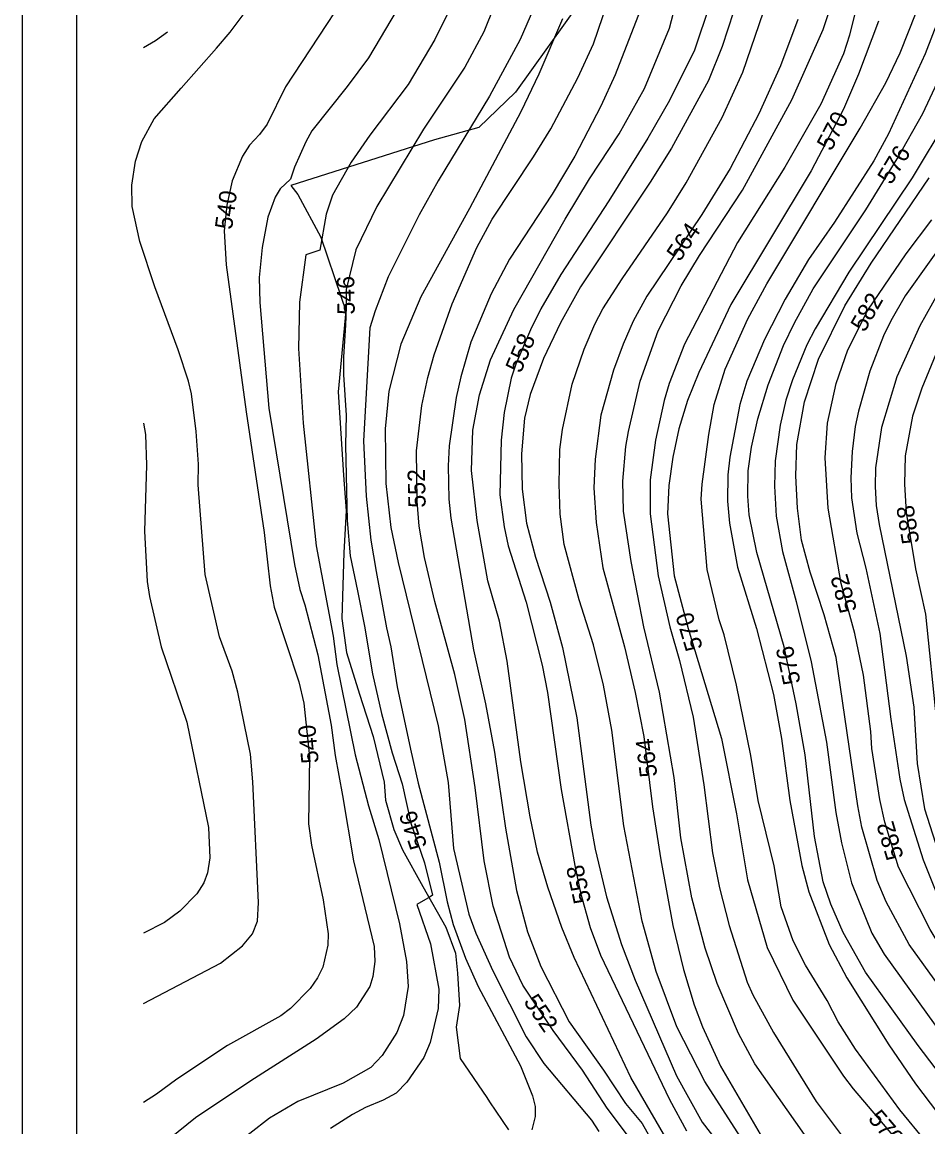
# Model space of a CAD drawing. Extents: x -709418 to -703832, y -1161719 to -1157826.
# Drawn here: x -709418 to -709000, y -1161138 to -1160629 of the extents above; entities that cross this region are included whole.
import ezdxf

# ---------------------------------------------------------------- set-up
doc = ezdxf.new("R2010")
doc.units = 0
for name, color, linetype in [('103_hranice KÚ', 7, 'Continuous'), ('120_vrstevnice hlavní', 7, 'Continuous'), ('121_vrstevnice hlavní_popis', 7, 'Continuous'), ('122_vrstevnice základní', 7, 'Continuous'), ('124_vrstevnice doplňková', 7, 'Continuous'), ('800_mřížka', 7, 'Continuous')]:
    doc.layers.add(name, color=color, linetype=linetype)

msp = doc.modelspace()

# ---------------------------------------------------------------- linework, layer by layer
at = {"layer": '103_hranice KÚ'}
msp.add_lwpolyline([(-709152.76, -1160608.68), (-709190.29, -1160661.38), (-709207.27, -1160677.68), (-709227.61, -1160683.32), (-709293.86, -1160704.4), (-709290.67, -1160708.55), (-709280.09, -1160728.22), (-709270.72, -1160755.76), (-709268.6, -1160762.02), (-709272.02, -1160799.36), (-709269.54, -1160837.72), (-709268.34, -1160854.2), (-709269.41, -1160873.36), (-709270.41, -1160903.76), (-709268.23, -1160919.43), (-709262.21, -1160938.65), (-709255.95, -1160958.22), (-709250.87, -1160979.18), (-709250.21, -1160987.55), (-709246.42, -1161000.99), (-709242.46, -1161010.31), (-709232.98, -1161027.29), (-709222.38, -1161046.02), (-709218.04, -1161058.04), (-709217.06, -1161067.22), (-709216.15, -1161082.04), (-709217.68, -1161092.12), (-709215.78, -1161106.54), (-709203.57, -1161124.53), (-709202.27, -1161126.44), (-709193.49, -1161139.37)], dxfattribs=at)
at = {"layer": '120_vrstevnice hlavní'}
for points in [[(-709254.71, -1160595.41), (-709296.28, -1160658.95), (-709304.81, -1160676.16), (-709308.28, -1160680.93), (-709312.91, -1160685.7), (-709316.09, -1160690.91), (-709320.88, -1160702.17), (-709323.4, -1160713.42), (-709324.66, -1160725.16), (-709323.61, -1160740.96), (-709314.5, -1160808.65), (-709306.11, -1160864.2), (-709303.36, -1160888.79), (-709301.48, -1160898.62), (-709290.2, -1160933.05), (-709287.89, -1160942.88), (-709285.28, -1160967.47), (-709285.72, -1160998.43), (-709284.41, -1161008.26), (-709278.92, -1161033.43), (-709276.6, -1161049.05), (-709276.75, -1161054.26), (-709279.06, -1161064.38), (-709281.52, -1161069.3), (-709284.99, -1161074.22), (-709294.1, -1161083.48), (-709298.44, -1161086.8), (-709323.03, -1161100.54), (-709346.47, -1161116.02), (-709355.72, -1161122.96), (-709361.7, -1161126.76)], [(-709089.87, -1160624.38), (-709095.07, -1160640.29), (-709101.44, -1160655.91), (-709118.51, -1160687.15), (-709128.34, -1160702.77), (-709160.45, -1160751.08), (-709169.57, -1160767.57), (-709177.38, -1160784.06), (-709183.6, -1160800.55), (-709186.2, -1160811.55), (-709187.5, -1160828.03), (-709187.21, -1160844.24), (-709185.19, -1160859.86), (-709181.14, -1160875.48), (-709174.34, -1160896.31), (-709168.7, -1160917.14), (-709162.05, -1160949.54), (-709155.54, -1160999), (-709153.66, -1161010), (-709148.45, -1161031.98), (-709141.51, -1161053.97), (-709135.14, -1161070.46), (-709116.19, -1161114.43), (-709104.33, -1161135.84), (-709079.02, -1161168.53)], [(-709168.7, -1160627.56), (-709179.55, -1160653.02), (-709187.94, -1160670.37), (-709211.51, -1160714.92), (-709233.93, -1160755.71), (-709243.19, -1160777.41), (-709248.69, -1160799.11), (-709250.42, -1160816.46), (-709250.13, -1160841.63), (-709247.82, -1160861.88), (-709244.35, -1160878.08), (-709225.98, -1160953.3), (-709221.35, -1160979.33), (-709218.89, -1161009.71), (-709211.8, -1161040.08), (-709208.62, -1161048.76), (-709200.81, -1161066.12), (-709185.48, -1161096.49), (-709177.23, -1161108.79), (-709155.25, -1161134.97), (-709151.92, -1161140.18)], [(-709023.04, -1160628.71), (-709032.3, -1160653.02), (-709039.1, -1160669.22), (-709053.99, -1160697.56), (-709091.02, -1160759.18), (-709105.78, -1160790.43), (-709111.13, -1160803.45), (-709115.04, -1160816.46), (-709117.78, -1160829.48), (-709119.66, -1160842.5), (-709120.24, -1160855.52), (-709117.21, -1160884.16), (-709110.7, -1160908.46), (-709095.36, -1160959.08), (-709088.42, -1160993.8), (-709083.36, -1161024.17), (-709074.35, -1161055.36), (-709062.5, -1161079.58), (-709039.24, -1161114.57), (-709034.76, -1161120.51), (-708995.85, -1161166.21)], [(-708986.59, -1161084.92), (-709008.87, -1161053.97), (-709019.43, -1161034.3), (-709023.62, -1161024.46), (-709030.71, -1160999.87), (-709032.59, -1160990.04), (-709042.57, -1160921.76), (-709048.07, -1160902.09), (-709054.57, -1160882.42), (-709058.48, -1160867.67), (-709060.36, -1160852.91), (-709061.08, -1160838.16), (-709060.65, -1160823.7), (-709057.18, -1160804.02), (-709050.67, -1160784.35), (-709038.52, -1160759.76), (-709026.37, -1160740.09), (-708999.75, -1160700.75)]]:
    msp.add_lwpolyline(points, dxfattribs=at)
at = {"layer": '122_vrstevnice základní'}
for points in [[(-709020.87, -1160572.01), (-709036.35, -1160635.08), (-709039.1, -1160643.76), (-709049.66, -1160666.9), (-709066.15, -1160695.83), (-709087.99, -1160730.54), (-709112.43, -1160777.41), (-709119.52, -1160795.63), (-709121.83, -1160803.45), (-709125.88, -1160821.67), (-709128.2, -1160839.9), (-709128.34, -1160855.52), (-709124.58, -1160884.16), (-709119.23, -1160907.59), (-709114.75, -1160923.21), (-709108.38, -1160949.25), (-709103.46, -1160980.49), (-709099.56, -1161011.73), (-709096.38, -1161027.93), (-709091.89, -1161045.29), (-709083.5, -1161071.33), (-709080.9, -1161077.11), (-709071.5, -1161094.47), (-709051.83, -1161126.29), (-709036.06, -1161147.12)], [(-709195.75, -1160610.49), (-709205, -1160633.63), (-709213.68, -1160649.83), (-709232.78, -1160678.47), (-709254.18, -1160714.05), (-709263.87, -1160734.02), (-709268.36, -1160752.24), (-709268.36, -1160760.2), (-709268.65, -1160768.73), (-709269.66, -1160783.2), (-709269.66, -1160791.58), (-709268.36, -1160810.1), (-709268.65, -1160823.98), (-709267.92, -1160858.7), (-709266.48, -1160874.9), (-709263.15, -1160891.1), (-709259.97, -1160907.3), (-709256.21, -1160929.29), (-709252.16, -1160947.51), (-709247.24, -1160965.74), (-709242.61, -1160979.91), (-709238.56, -1160998.14), (-709232.34, -1161016.36), (-709228.58, -1161031.26), (-709229.59, -1161031.98), (-709235.75, -1161035.57), (-709229.45, -1161053.68), (-709225.69, -1161074.51), (-709225.98, -1161083.48), (-709229.59, -1161099.1), (-709232.63, -1161106.04), (-709240.44, -1161117.47), (-709245.36, -1161122.39), (-709251.29, -1161125.71), (-709259.39, -1161129.04), (-709265.47, -1161132.22), (-709275.59, -1161138.73)], [(-709136.88, -1161144.23), (-709148.16, -1161129.33), (-709159.44, -1161111.83), (-709173.04, -1161093.6), (-709186.92, -1161072.77), (-709193.14, -1161059.76), (-709200.67, -1161036.32), (-709204.72, -1161015.49), (-709208.91, -1160981.65), (-709213.68, -1160950.4), (-709218.31, -1160929.57), (-709227.57, -1160896.02), (-709232.2, -1160875.77), (-709234.66, -1160861.3), (-709235.67, -1160849.73), (-709235.96, -1160826.59), (-709233.5, -1160805.76), (-709230.75, -1160792.74), (-709227.86, -1160782.33), (-709219.47, -1160758.89), (-709208.19, -1160732.86), (-709201.1, -1160719.84), (-709182.01, -1160691.2), (-709174.05, -1160678.18), (-709161.61, -1160654.75), (-709154.38, -1160639.13), (-709143.48, -1160606.97)], [(-709046.18, -1161156.96), (-709080.03, -1161108.93), (-709087.55, -1161095.05), (-709097.39, -1161071.91), (-709102.89, -1161055.71), (-709109.1, -1161032.56), (-709114.17, -1161004.79), (-709117.2, -1160977.02), (-709124, -1160937.68), (-709131.23, -1160907.59), (-709137.02, -1160877.5), (-709140.49, -1160854.36), (-709140.93, -1160840.47), (-709139.48, -1160824.56), (-709138.32, -1160817.62), (-709132.83, -1160794.48), (-709124.58, -1160771.33), (-709114.02, -1160750.51), (-709105.49, -1160736.62), (-709085.67, -1160706.53), (-709062.96, -1160664.88), (-709048.5, -1160632.48), (-709040.83, -1160609.33)], [(-709120.97, -1161143.07), (-709137.17, -1161115.3), (-709163.35, -1161060.04), (-709168.99, -1161046.16), (-709175.5, -1161027.64), (-709180.12, -1161011.44), (-709183.6, -1160995.24), (-709187.94, -1160969.79), (-709194.16, -1160923.5), (-709197.77, -1160904.99), (-709203.12, -1160886.47), (-709208.04, -1160858.7), (-709210.65, -1160835.56), (-709209.92, -1160817.04), (-709206.88, -1160800.84), (-709201.82, -1160784.64), (-709191.12, -1160761.5), (-709167.4, -1160719.84), (-709156.26, -1160701.33), (-709142.52, -1160680.5), (-709130.95, -1160659.67), (-709119.37, -1160631.9), (-709114.02, -1160611.07)], [(-708992.09, -1160619.46), (-709001.49, -1160643.76), (-709018.41, -1160680.5), (-709025.21, -1160692.94), (-709043.29, -1160721.29), (-709055.3, -1160738.5), (-709066, -1160756.72), (-709075.55, -1160775.24), (-709083.65, -1160794.48), (-709086.97, -1160805.18), (-709091.6, -1160829.48), (-709092.47, -1160837.58), (-709092.61, -1160849.73), (-709091.75, -1160859.86), (-709087.99, -1160880.11), (-709079.31, -1160908.46), (-709071.35, -1160938.83), (-709067.74, -1160959.08), (-709063.83, -1160987.72), (-709058.33, -1161017.52), (-709055.15, -1161029.67), (-709045.75, -1161053.97), (-709037.65, -1161069.3), (-709018.27, -1161100.26), (-709005.97, -1161118.19), (-708995.85, -1161131.5)], [(-709318.26, -1160937.68), (-709320.86, -1160928.13), (-709326.79, -1160912.22), (-709333.3, -1160883.58), (-709336.63, -1160842.21), (-709336.49, -1160832.66), (-709337.5, -1160817.62), (-709339.67, -1160800.26), (-709340.97, -1160794.48), (-709345.74, -1160780.01), (-709356.59, -1160751.08), (-709363.4, -1160730.16), (-709367.05, -1160714.01), (-709367.1, -1160704.14), (-709365.45, -1160693.07), (-709362.6, -1160684.04), (-709356.83, -1160673.68), (-709344.42, -1160659.49), (-709328.11, -1160641.08), (-709321.76, -1160633.76), (-709315.8, -1160625.68)], [(-709244.93, -1160623.22), (-709258.09, -1160645.49), (-709267.92, -1160658.8), (-709284.12, -1160679.2), (-709287.02, -1160684.26), (-709292.22, -1160695.83), (-709293.96, -1160701.47), (-709298.73, -1160705.81), (-709301.05, -1160709.72), (-709304.52, -1160718.97), (-709307.12, -1160732.86), (-709308.42, -1160746.74), (-709308.14, -1160758.32), (-709303.94, -1160806.92), (-709292.22, -1160878.95), (-709289.77, -1160890.52), (-709287.45, -1160897.46), (-709281.38, -1160920.61), (-709275.3, -1160953.01), (-709273.42, -1160966.89), (-709270.09, -1160985.41), (-709265.03, -1161015.49), (-709255.48, -1161054.84), (-709255.2, -1161061.78), (-709256.06, -1161068.72), (-709257.51, -1161073.35), (-709263.59, -1161082.9), (-709269.23, -1161088.25), (-709282.24, -1161097.65), (-709312.33, -1161116.75), (-709337.79, -1161133.81), (-709361.7, -1161153.18)], [(-709221.93, -1160625.82), (-709227.57, -1160637.1), (-709239.86, -1160657.79), (-709257.51, -1160681.22), (-709266.04, -1160693.66), (-709274.72, -1160708.85), (-709277.61, -1160717.53), (-709280.48, -1160734.12), (-709287.02, -1160736.27), (-709289.91, -1160758.03), (-709290.34, -1160779.43), (-709288.17, -1160813.86), (-709282.24, -1160870.27), (-709274.43, -1160911.93), (-709272.7, -1160924.95), (-709264.16, -1160966.6), (-709258.09, -1160990.04), (-709253.32, -1161005.66), (-709243.77, -1161044.42), (-709240.59, -1161061.78), (-709239.86, -1161073.35), (-709241.89, -1161086.66), (-709245.07, -1161094.47), (-709251.72, -1161105.17), (-709257.08, -1161110.67), (-709269.81, -1161117.9), (-709290.63, -1161126.29), (-709303.65, -1161133.96), (-709321.88, -1161148.13)], [(-709182.01, -1160622.93), (-709188.22, -1160637.1), (-709202.26, -1160663.14), (-709225.98, -1160702.19), (-709234.8, -1160717.81), (-709248.98, -1160746.46), (-709255.05, -1160762.08), (-709257.51, -1160769.89), (-709260.4, -1160821.96), (-709259.1, -1160847.42), (-709257.08, -1160867.67), (-709254.47, -1160882.13), (-709249.84, -1160908.17), (-709247.82, -1160916.85), (-709244.93, -1160935.36), (-709238.71, -1160964), (-709235.23, -1160979.62), (-709225.54, -1161016.07), (-709221.78, -1161034.3), (-709219.03, -1161044.71), (-709213.39, -1161060.33), (-709207.46, -1161073.35), (-709188.08, -1161109.8), (-709182.44, -1161123.69), (-709181.28, -1161128.6), (-709181.28, -1161133.23), (-709182.73, -1161139.31)], [(-709132.83, -1160623.8), (-709144.4, -1160653.3), (-709151.05, -1160667.77), (-709163.06, -1160690.91), (-709173.47, -1160708.27), (-709193.14, -1160738.35), (-709201.53, -1160754.27), (-709210.93, -1160776.54), (-709215.56, -1160792.45), (-709217.73, -1160802), (-709220.91, -1160824.27), (-709221.35, -1160833.53), (-709221.06, -1160848.86), (-709220.19, -1160857.54), (-709209.63, -1160918.29), (-709204.14, -1160943.17), (-709199.94, -1160965.45), (-709194.88, -1161000.45), (-709189.82, -1161029.09), (-709184.75, -1161048.18), (-709178.68, -1161064.09), (-709165.66, -1161089.55), (-709149.75, -1161111.83), (-709139.62, -1161127.16), (-709131.96, -1161136.42), (-709123.28, -1161151.75)], [(-709100.72, -1160620.9), (-709107.8, -1160642.02), (-709119.37, -1160665.17), (-709129.35, -1160682.52), (-709147.29, -1160711.45), (-709169.42, -1160745.3), (-709178.68, -1160761.21), (-709183.45, -1160770.76), (-709190.25, -1160786.67), (-709192.28, -1160793.03), (-709195.6, -1160808.94), (-709196.9, -1160821.67), (-709197.48, -1160846.84), (-709195.6, -1160861.59), (-709193.72, -1160870.27), (-709185.48, -1160896.31), (-709178.1, -1160925.24), (-709175.64, -1160937.96), (-709169.28, -1160982.52), (-709163.06, -1161017.52), (-709160.31, -1161030.25), (-709155.97, -1161046.16), (-709151.2, -1161058.89)], [(-709086.83, -1161142.49), (-709103.03, -1161117.03), (-709115.9, -1161091.87), (-709125.45, -1161066.41), (-709131.96, -1161043.27), (-709140.35, -1160999.29), (-709145.99, -1160955.32), (-709149.75, -1160934.49), (-709154.38, -1160915.98), (-709161.03, -1160895.15), (-709167.83, -1160869.69), (-709169.71, -1160855.81), (-709170.14, -1160841.92), (-709169.85, -1160826.01), (-709168.7, -1160816.75), (-709164.21, -1160795.92), (-709158.72, -1160779.72), (-709153.8, -1160768.15), (-709150.04, -1160761.21), (-709141.22, -1160747.32), (-709120.24, -1160716.95), (-709111.71, -1160703.06), (-709095.07, -1160672.98), (-709085.53, -1160652.15), (-709075.98, -1160624.38)], [(-709001.06, -1161144.81), (-709013.21, -1161130.2), (-709033.6, -1161102.14), (-709041.56, -1161089.55), (-709046.62, -1161079.72), (-709056.74, -1161063.52), (-709062.29, -1161052.26), (-709067.83, -1161036.6), (-709071.06, -1161017.81), (-709078.44, -1160987.72), (-709081.91, -1160966.89), (-709088.42, -1160934.49), (-709094.21, -1160911.35), (-709096.52, -1160904.41), (-709102.02, -1160881.26), (-709104.77, -1160848.86), (-709104.33, -1160841.92), (-709101.29, -1160819.07), (-709098.84, -1160805.18), (-709093.77, -1160788.98), (-709083.21, -1160765.84), (-709074.54, -1160749.64), (-709031.43, -1160677.89), (-709019.71, -1160657.06), (-709013.06, -1160643.18), (-709005.68, -1160624.66)], [(-709060.22, -1160627.85), (-709068.17, -1160649.25), (-709078.15, -1160671.38), (-709091.46, -1160696.55), (-709104.48, -1160717.67), (-709129.79, -1160755.28), (-709136.15, -1160766.85), (-709140.78, -1160777.41), (-709145.12, -1160789.41), (-709151.05, -1160810.1), (-709153.66, -1160830.35), (-709154.23, -1160843.66), (-709153.08, -1160859.57), (-709150.04, -1160880.4), (-709140.06, -1160916.85), (-709135.14, -1160937.96), (-709131.23, -1160958.21), (-709127.19, -1160990.61), (-709123.42, -1161014.92), (-709117.78, -1161045.29), (-709112.86, -1161065.54), (-709107.95, -1161081.74), (-709104.19, -1161091.87), (-709095.8, -1161110.09), (-709077.57, -1161141.33)], [(-709028.97, -1161066.7), (-709039.39, -1161048.47), (-709045.03, -1161035.46), (-709048.5, -1161025.04), (-709052.55, -1161004.21), (-709056.89, -1160966.6), (-709060.94, -1160943.17), (-709066.58, -1160916.85), (-709079.16, -1160873.45), (-709082.64, -1160856.09), (-709083.21, -1160847.42), (-709083.07, -1160835.84), (-709081.62, -1160824.85), (-709078.59, -1160811.83), (-709073.81, -1160796.21), (-709066.87, -1160777.99), (-709061.81, -1160767.57), (-709053.13, -1160751.95), (-709028.83, -1160715.5), (-709014.36, -1160692.07), (-709002.65, -1160671.24), (-708988.04, -1160640)], [(-708991.07, -1160673.55), (-709007.56, -1160700.75), (-709036.64, -1160744.29), (-709052.26, -1160770.32), (-709056.02, -1160777.7), (-709062.67, -1160793.9), (-709065.71, -1160803.16), (-709068.32, -1160814.73), (-709070.63, -1160831.22), (-709070.92, -1160842.79), (-709070.2, -1160856.67), (-709067.3, -1160872.87), (-709060.94, -1160896.02), (-709054.14, -1160923.79), (-709047.05, -1160960.82), (-709042.71, -1160993.22), (-709040.11, -1161007.1), (-709035.48, -1161025.62), (-709026.08, -1161048.76), (-709020.44, -1161058.45), (-708989.05, -1161101.99)], [(-708975.31, -1160705.38), (-709010.75, -1160755.13), (-709017.4, -1160766.71), (-709020.73, -1160773.65), (-709027.09, -1160789.85), (-709032.3, -1160808.36), (-709033.74, -1160815.31), (-709035.19, -1160826.88), (-709035.77, -1160839.03), (-709035.48, -1160848.29), (-709033.02, -1160864.49)], [(-709037.22, -1160780.01), (-709027.96, -1160761.79), (-709010.31, -1160735.75), (-708998.45, -1160720.13)], [(-708995.27, -1160753.4), (-709003.95, -1160769.02), (-709014.65, -1160792.45), (-709021.6, -1160815.88), (-709024.34, -1160834.4), (-709024.63, -1160843.08), (-709024.05, -1160851.76), (-709022.75, -1160860.44), (-709010.31, -1160921.19), (-709006.7, -1160944.62), (-709005.25, -1160970.65), (-709001.78, -1160991.48), (-708994.26, -1161014.92)], [(-708994.4, -1160776.83), (-709003.08, -1160797.66), (-709007.42, -1160810.68), (-709010.75, -1160828.9), (-709011.04, -1160841.92), (-709010.31, -1160854.94), (-709005.97, -1160880.97), (-709001.35, -1160901.8), (-708996.28, -1160951.27)], [(-708893.15, -1161139.16), (-708904.72, -1161135.11), (-708913.98, -1161131.06), (-708931.34, -1161121.52), (-708946.23, -1161111.97), (-708958.96, -1161101.27), (-708973.28, -1161086.08), (-708986.73, -1161067.85), (-708999.18, -1161047.03), (-709013.78, -1161018.39), (-709020.15, -1160997.56), (-709022.46, -1160987.14), (-709026.08, -1160963.71), (-709026.51, -1160955.9), (-709029.98, -1160929.86), (-709033.89, -1160910.77), (-709040.25, -1160887.63), (-709046.18, -1160852.91), (-709047.63, -1160829.77), (-709046.47, -1160813.86), (-709042.57, -1160795.63), (-709037.22, -1160780.01)], [(-709361.7, -1160813.76), (-709360.93, -1160819.07), (-709360.35, -1160833.24), (-709361.36, -1160863.62), (-709360.06, -1160886.76), (-709359.05, -1160893.7), (-709353.7, -1160916.85), (-709341.84, -1160951.56), (-709331.86, -1161000.16), (-709331.13, -1161014.05), (-709332.29, -1161020.99), (-709334.03, -1161025.62), (-709337.21, -1161030.68), (-709345.02, -1161038.64), (-709352.11, -1161043.84), (-709361.7, -1161048.71)], [(-709033.02, -1160864.49), (-709028.83, -1160880.69), (-709022.46, -1160910.77), (-709017.4, -1160950.11), (-709013.21, -1160977.89), (-709011.18, -1160987.14), (-709002.5, -1161014.92), (-708995.99, -1161031.11)], [(-709361.7, -1161081.1), (-709326.22, -1161062.65), (-709316.09, -1161054.55), (-709311.61, -1161049.05), (-709309.29, -1161043.27), (-709308.71, -1161034.59), (-709311.32, -1160979.04), (-709312.47, -1160966.31), (-709318.26, -1160937.68)], [(-709151.2, -1161058.89), (-709119.37, -1161125.42), (-709111.56, -1161139.89)], [(-708969.23, -1161142.64), (-708983.7, -1161128.17), (-709004.82, -1161100.55), (-709028.97, -1161066.7)]]:
    msp.add_lwpolyline(points, dxfattribs=at)
at = {"layer": '124_vrstevnice doplňková'}
msp.add_lwpolyline([(-709361.7, -1160640.74), (-709356.3, -1160637.54), (-709350.66, -1160633.49)], dxfattribs=at)
at = {"layer": '800_mřížka'}
for points in [[(-703832.2, -1161718.9), (-703832.2, -1157825.62), (-709417.73, -1157825.62), (-709417.73, -1161718.9)], [(-703857.2, -1161693.9), (-703857.2, -1157850.62), (-709392.73, -1157850.62), (-709392.73, -1161693.9)]]:
    msp.add_lwpolyline(points, close=True, dxfattribs=at)

# ---------------------------------------------------------------- texts
at = {"layer": '121_vrstevnice hlavní_popis'}
for s, rotation, p in [('570', 62.3906, (-709044.81, -1160688.87)), ('576', 58.7275, (-709017.21, -1160704.39)), ('540', 82.1705, (-709321.03, -1160724.94)), ('564', 55.8876, (-709114.65, -1160739.82)), ('546', 90.8938, (-709264.39, -1160763.81)), ('582', 60.1639, (-709029.46, -1160772.33)), ('558', 67.0486, (-709187.93, -1160791.19)), ('552', 91.3372, (-709231.69, -1160852.71)), ('588', 99.1682, (-709004.15, -1160868.78)), ('582', 105.3775, (-709032.85, -1160899.93)), ('570', 106.741, (-709103.91, -1160917.33)), ('576', 102.1974, (-709058.89, -1160933.34)), ('540', 95.3577, (-709280.98, -1160970.22)), ('564', 97.0146, (-709124.95, -1160976.41)), ('546', 108.5209, (-709230.95, -1161008.57)), ('582', 106.4684, (-709011.36, -1161013.67)), ('558', 102.4735, (-709155.43, -1161034.16)), ('552', 304.0689, (-709186.86, -1161080.32)), ('570', 310.34, (-709028.22, -1161134.38))]:
    msp.add_text(s, height=8, rotation=rotation, dxfattribs=at).set_placement(p)

doc.saveas('drawing.dxf')
